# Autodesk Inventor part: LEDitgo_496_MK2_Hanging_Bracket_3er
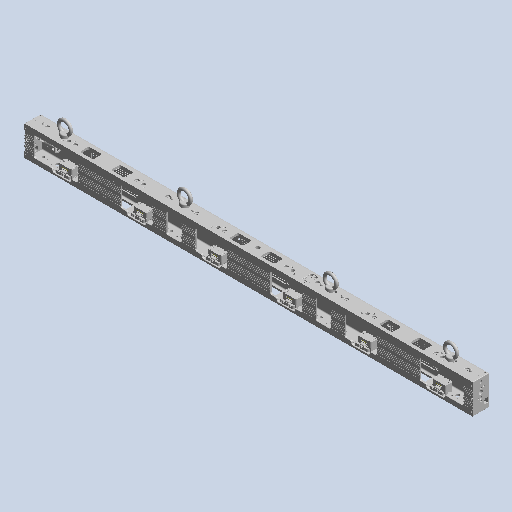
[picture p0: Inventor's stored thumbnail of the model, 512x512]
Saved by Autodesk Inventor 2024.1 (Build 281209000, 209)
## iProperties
Company: LEDitgo Videowall Germany GmbH
Created: 2024-11
Part Number: LEDitgo_496_MK2_Hanging_Bracket_3er
Material: Allgemein
Document SubType Name: Modellieren
Designer: Tobias Jandausch
Appearance: Vorgabe
Project: 496 MK2 Serie
Description: 496 MK2 Hanging Bracket 3er
Sending System: SIEMENS PLM Software NX 12.0
Preprocessor: ST-DEVELOPER v16.7
Title: LEDitgo_496_MK2_Hanging_Bracket_3er
Revision Number: 01
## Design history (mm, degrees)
feature "Basis1"
feature "KM3X22" [Basis]
feature "KM3X22:1" [Basis]
feature "KM3X22:2" [Basis]
feature "KM3X22:3" [Basis]
feature "Basis6"
feature "Basis7"
feature "Basis8"
feature "Basis9"
feature "Basis10"
feature "12X4-S" [Basis]
feature "12X4-S:1" [Basis]
feature "12X4-S:2" [Basis]
feature "12X4-S:3" [Basis]
feature "12X4-S:4" [Basis]
feature "KM3X22:4" [Basis]
feature "KM3X22:5" [Basis]
feature "KM3X22:6" [Basis]
feature "Basis19"
feature "KM3X22:7" [Basis]
feature "KM3X22:8" [Basis]
feature "KM3X22:9" [Basis]
feature "Basis23"
feature "KM3X22:10" [Basis]
feature "KM3X22:11" [Basis]
feature "KM3X22:12" [Basis]
feature "KM3X22:13" [Basis]
feature "Basis28"
feature "Basis29"
feature "PTM3.00-0.00" [Basis]
feature "Basis31"
feature "Basis32"
feature "Basis33"
feature "PTM3.00-0.00:1" [Basis]
feature "Basis35"
feature "Basis36"
feature "PTM3.00-0.00:2" [Basis]
feature "Basis38"
feature "PTM3.00-0.00:3" [Basis]
feature "Basis40"
feature "Basis41"
feature "KM3X22:14" [Basis]
feature "KM3X22:15" [Basis]
feature "Basis44"
feature "Basis45"
feature "Basis46"
feature "Basis47"
feature "Basis48"
feature "Basis49"
feature "Basis50"
feature "Basis51"
feature "Basis52"
feature "PTM3.00-0.00:4" [Basis]
feature "Basis54"
feature "KM3X22:16" [Basis]
feature "Basis56"
feature "PTM3.00-0.00:5" [Basis]
feature "KM3X22:17" [Basis]
feature "PTM3.00-0.00:6" [Basis]
feature "PTM3.00-0.00:7" [Basis]
feature "Basis61"
feature "Basis62"
feature "Basis63"
feature "XT-DWZ" [Basis]
feature "XT-DWZ:1" [Basis]
feature "Basis66"
feature "Basis67"
feature "PTM3.00-0.00:8" [Basis]
feature "Basis69"
feature "Basis70"
feature "Basis71"
feature "Basis72"
feature "Basis73"
feature "Basis74"
feature "Basis75"
feature "XT-DWZ:2" [Basis]
feature "Basis77"
feature "Basis78"
feature "PTM3.00-0.00:9" [Basis]
feature "Basis80"
feature "Basis81"
feature "Basis82"
feature "Basis83"
feature "Basis84"
feature "KM3X22:18" [Basis]
feature "Basis86"
feature "KM3X22:19" [Basis]
feature "Basis88"
feature "PTM3.00-0.00:10" [Basis]
feature "PTM3.00-0.00:11" [Basis]
feature "Basis91"
feature "Basis92"
feature "Basis93"
feature "XT-DWZ:3" [Basis]
feature "Basis95"
feature "Basis96"
feature "PTM3.00-0.00:12" [Basis]
feature "Basis98"
feature "KM3X22:20" [Basis]
feature "KM3X22:21" [Basis]
feature "PTM3.00-0.00:13" [Basis]
feature "Basis102"
feature "KM3X22:22" [Basis]
feature "PTM3.00-0.00:14" [Basis]
feature "PTM3.00-0.00:15" [Basis]
feature "Basis106"
feature "KM3X22:23" [Basis]
feature "KM3X22:24" [Basis]
feature "Basis109"
feature "KM3X22:25" [Basis]
feature "12X4-S:5" [Basis]
feature "12X4-S:6" [Basis]
feature "12X4-S:7" [Basis]
feature "12X4-S:8" [Basis]
feature "12X4-S:9" [Basis]
feature "Basis116"
feature "KM3X22:26" [Basis]
feature "Basis118"
feature "KM3X22:27" [Basis]
feature "PTM3.00-0.00:16" [Basis]
feature "Basis121"
feature "Basis122"
feature "Basis123"
feature "Basis124"
feature "PTM3.00-0.00:17" [Basis]
feature "Basis126"
feature "PTM3.00-0.00:18" [Basis]
feature "XT-DWZ:4" [Basis]
feature "Basis129"
feature "XT-DWZ:5" [Basis]
feature "12X4-S:10" [Basis]
feature "PTM3.00-0.00:19" [Basis]
feature "12X4-S:11" [Basis]
feature "Basis134"
feature "Basis135"
feature "KM3X22:28" [Basis]
feature "KM3X22:29" [Basis]
feature "KM3X22:30" [Basis]
feature "Basis139"
feature "Basis140"
feature "Basis141"
feature "Basis142"
feature "Basis143"
feature "PTM3.00-0.00:20" [Basis]
feature "PTM3.00-0.00:21" [Basis]
feature "KM3X22:31" [Basis]
feature "KM3X22:32" [Basis]
feature "Basis148"
feature "KM3X22:33" [Basis]
feature "Basis150"
feature "Basis151"
feature "Basis152"
feature "Basis153"
feature "12X4-S:12" [Basis]
feature "KM3X22:34" [Basis]
feature "12X4-S:13" [Basis]
feature "PTM3.00-0.00:22" [Basis]
feature "12X4-S:14" [Basis]
feature "Basis159"
feature "KM3X22:35" [Basis]
feature "XT-DWZ:6" [Basis]
feature "KM3X22:36" [Basis]
feature "KM3X22:37" [Basis]
feature "PTM3.00-0.00:23" [Basis]
feature "KM3X22:38" [Basis]
feature "Basis166"
feature "KM3X22:39" [Basis]
feature "PM4X10" [Basis]
feature "Basis169"
feature "Basis170"
feature "Basis171"
feature "Basis172"
feature "Basis173"
feature "KM3X22:40" [Basis]
feature "KM3X22:41" [Basis]
feature "KM3X22:42" [Basis]
feature "KM3X22:43" [Basis]
feature "KM3X22:44" [Basis]
feature "KM3X22:45" [Basis]
feature "KM3X22:46" [Basis]
feature "Basis181"
feature "KM3X22:47" [Basis]
feature "KM3X22:48" [Basis]
feature "KM3X22:49" [Basis]
feature "KM3X22:50" [Basis]
feature "KM3X22:51" [Basis]
feature "Basis187"
feature "Basis188"
feature "KM3X22:52" [Basis]
feature "XT-DWZ:7" [Basis]
feature "KM3X22:53" [Basis]
feature "KM3X22:54" [Basis]
feature "XT-DWZ:8" [Basis]
feature "PM4X10:1" [Basis]
feature "KM3X22:55" [Basis]
feature "KM3X22:56" [Basis]
feature "Basis197"
feature "KM3X22:57" [Basis]
feature "Basis199"
feature "Basis200"
feature "Basis201"
feature "Basis202"
feature "Basis203"
feature "Basis204"
feature "Basis205"
feature "Basis206"
feature "Basis207"
feature "Basis208"
feature "Basis209"
feature "Basis210"
feature "Basis211"
feature "Basis212"
node "Volumenkörper109"
node "Volumenkörper"
node "Flächenkörper"
node "Volumenkörper1"
node "Volumenkörper2"
node "Volumenkörper3"
node "Volumenkörper4"
node "Volumenkörper110"
node "Volumenkörper111"
node "Volumenkörper112"
node "Volumenkörper113"
node "Volumenkörper114"
node "Volumenkörper5"
node "Volumenkörper6"
node "Volumenkörper7"
node "Volumenkörper8"
node "Volumenkörper9"
node "Volumenkörper10"
node "Volumenkörper11"
node "Volumenkörper12"
node "Volumenkörper115"
node "Volumenkörper13"
node "Volumenkörper14"
node "Volumenkörper15"
node "Volumenkörper116"
node "Volumenkörper16"
node "Volumenkörper17"
node "Volumenkörper18"
node "Volumenkörper19"
node "Volumenkörper117"
node "Volumenkörper118"
node "Volumenkörper20"
node "Volumenkörper119"
node "Volumenkörper120"
node "Volumenkörper121"
node "Volumenkörper21"
node "Volumenkörper122"
node "Volumenkörper123"
node "Volumenkörper22"
node "Volumenkörper124"
node "Volumenkörper23"
node "Volumenkörper125"
node "Volumenkörper126"
node "Volumenkörper24"
node "Volumenkörper25"
node "Volumenkörper127"
node "Volumenkörper128"
node "Volumenkörper129"
node "Volumenkörper130"
node "Volumenkörper131"
node "Volumenkörper132"
node "Volumenkörper133"
node "Volumenkörper134"
node "Volumenkörper135"
node "Volumenkörper26"
node "Volumenkörper136"
node "Volumenkörper27"
node "Volumenkörper137"
node "Volumenkörper28"
node "Volumenkörper29"
node "Volumenkörper30"
node "Volumenkörper31"
node "Volumenkörper138"
node "Volumenkörper139"
node "Volumenkörper140"
node "Volumenkörper32"
node "Volumenkörper33"
node "Volumenkörper141"
node "Volumenkörper142"
node "Volumenkörper34"
node "Volumenkörper143"
node "Volumenkörper144"
node "Volumenkörper145"
node "Volumenkörper146"
node "Volumenkörper147"
node "Volumenkörper148"
node "Volumenkörper149"
node "Volumenkörper35"
node "Volumenkörper150"
node "Volumenkörper151"
node "Volumenkörper36"
node "Volumenkörper152"
node "Volumenkörper153"
node "Volumenkörper154"
node "Volumenkörper155"
node "Volumenkörper156"
node "Volumenkörper37"
node "Volumenkörper157"
node "Volumenkörper38"
node "Volumenkörper158"
node "Volumenkörper39"
node "Volumenkörper40"
node "Volumenkörper159"
node "Volumenkörper160"
node "Volumenkörper161"
node "Volumenkörper41"
node "Volumenkörper162"
node "Volumenkörper163"
node "Volumenkörper42"
node "Volumenkörper164"
node "Volumenkörper43"
node "Volumenkörper44"
node "Volumenkörper45"
node "Volumenkörper165"
node "Volumenkörper46"
node "Volumenkörper47"
node "Volumenkörper48"
node "Volumenkörper166"
node "Volumenkörper49"
node "Volumenkörper50"
node "Volumenkörper167"
node "Volumenkörper51"
node "Volumenkörper52"
node "Volumenkörper53"
node "Volumenkörper54"
node "Volumenkörper55"
node "Volumenkörper56"
node "Volumenkörper168"
node "Volumenkörper57"
node "Volumenkörper169"
node "Volumenkörper58"
node "Volumenkörper59"
node "Volumenkörper170"
node "Volumenkörper171"
node "Volumenkörper172"
node "Volumenkörper173"
node "Volumenkörper60"
node "Volumenkörper174"
node "Volumenkörper61"
node "Volumenkörper62"
node "Volumenkörper175"
node "Volumenkörper63"
node "Volumenkörper64"
node "Volumenkörper65"
node "Volumenkörper66"
node "Volumenkörper176"
node "Volumenkörper177"
node "Volumenkörper67"
node "Volumenkörper68"
node "Volumenkörper69"
node "Volumenkörper178"
node "Volumenkörper179"
node "Volumenkörper180"
node "Volumenkörper181"
node "Volumenkörper182"
node "Volumenkörper70"
node "Volumenkörper71"
node "Volumenkörper72"
node "Volumenkörper73"
node "Volumenkörper183"
node "Volumenkörper74"
node "Volumenkörper184"
node "Volumenkörper185"
node "Volumenkörper186"
node "Volumenkörper187"
node "Volumenkörper75"
node "Volumenkörper76"
node "Volumenkörper77"
node "Volumenkörper78"
node "Volumenkörper79"
node "Volumenkörper188"
node "Volumenkörper80"
node "Volumenkörper81"
node "Volumenkörper82"
node "Volumenkörper83"
node "Volumenkörper84"
node "Volumenkörper85"
node "Volumenkörper189"
node "Volumenkörper86"
node "Volumenkörper87"
node "Volumenkörper190"
node "Volumenkörper191"
node "Volumenkörper192"
node "Volumenkörper193"
node "Volumenkörper194"
node "Volumenkörper88"
node "Volumenkörper89"
node "Volumenkörper90"
node "Volumenkörper91"
node "Volumenkörper92"
node "Volumenkörper93"
node "Volumenkörper94"
node "Volumenkörper195"
node "Volumenkörper95"
node "Volumenkörper96"
node "Volumenkörper97"
node "Volumenkörper98"
node "Volumenkörper99"
node "Volumenkörper196"
node "Volumenkörper197"
node "Volumenkörper100"
node "Volumenkörper101"
node "Volumenkörper102"
node "Volumenkörper103"
node "Volumenkörper104"
node "Volumenkörper105"
node "Volumenkörper106"
node "Volumenkörper107"
node "Volumenkörper198"
node "Volumenkörper108"
node "Volumenkörper199"
node "Volumenkörper200"
node "Volumenkörper201"
node "Volumenkörper202"
node "Volumenkörper203"
node "Volumenkörper204"
node "Volumenkörper205"
node "Volumenkörper206"
node "Volumenkörper207"
node "Volumenkörper208"
node "Volumenkörper209"
node "Volumenkörper210"
node "Volumenkörper211"
node "Volumenkörper212"
